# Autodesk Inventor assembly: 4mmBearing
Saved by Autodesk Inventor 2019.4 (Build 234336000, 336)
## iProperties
Created: 2020-04
Part Number: 4mmBearing
Document SubType Name: Assembly
Designer: Administrator
Title: 4mmBearing v4
Author: Administrator
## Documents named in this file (2)
- c:\worker\convert-fusion-r03\tmp\job-1\48\output\files\ccae6ef3-9f0e-42ff-b199-3a2c6474057a\4mmBearing v4_1.iam
- c:\worker\convert-fusion-r03\tmp\job-1\48\output\files\ccae6ef3-9f0e-42ff-b199-3a2c6474057a\4mmBearing.ipt
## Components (1 placed, 1 different names)
1. 4mmBearing:1
